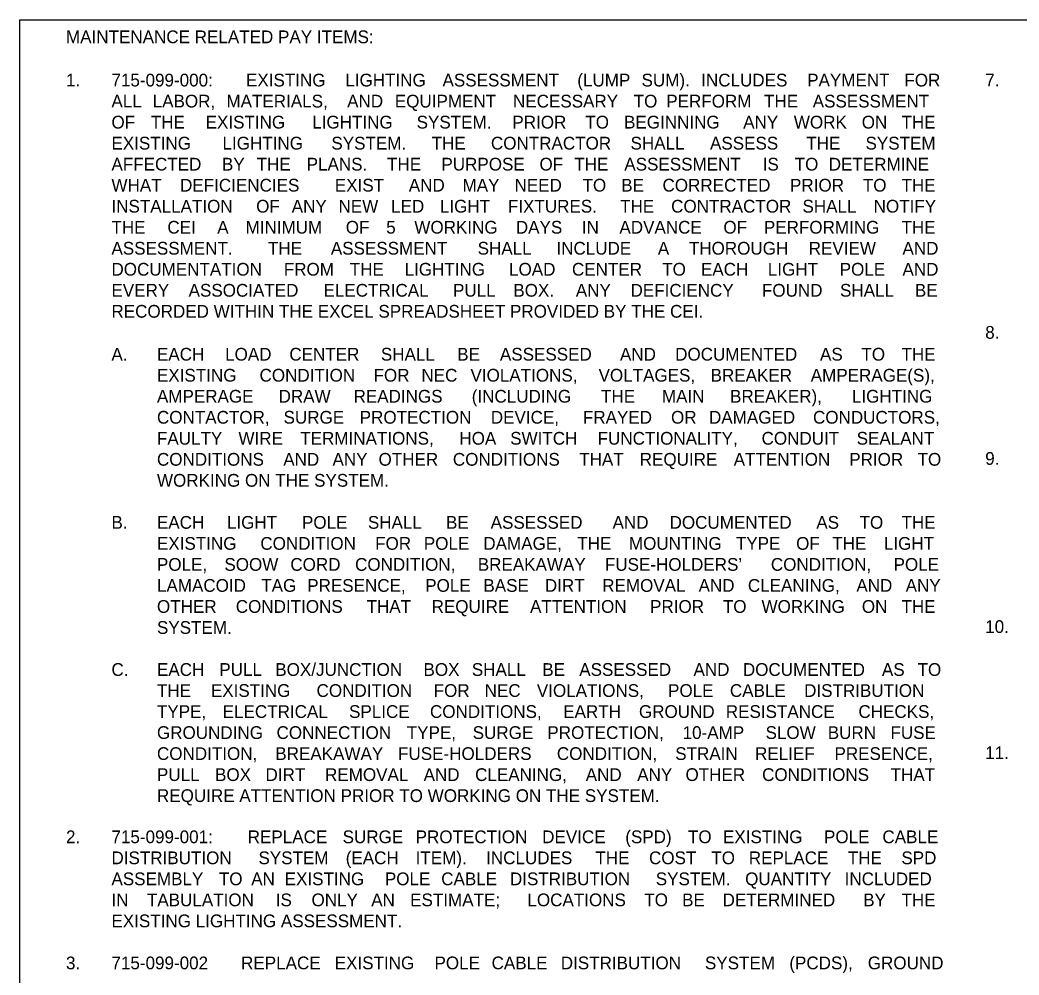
# Model space of a CAD drawing. Extents: x -55 to 2471539, y -90 to 3608906.
# Drawn here: x 0 to 543, y 440 to 960 of the extents above; entities that cross this region are included whole.
import ezdxf

# ---------------------------------------------------------------- set-up
doc = ezdxf.new("R2010")
doc.units = 0
doc.layers.add('NonPlottingEle_dp', color=7, linetype='Continuous')
doc.layers.add('TextNotes', color=7, linetype='Continuous')

msp = doc.modelspace()

# ---------------------------------------------------------------- linework, layer by layer
at = {"layer": 'NonPlottingEle_dp'}
msp.add_lwpolyline([(0, 0), (0, 960), (1540, 960), (1540, 0)], dxfattribs=at)

# ---------------------------------------------------------------- texts
at = {"layer": 'TextNotes'}
for s, p in [('MAINTENANCE RELATED PAY ITEMS:', (25.02, 947.36)), ('1.', (25.02, 923.83)), ('715-099-000: ', (49.75, 923.83)), ('EXISTING ', (122.93, 923.83)), ('LIGHTING ', (176.95, 923.83)), ('ASSESSMENT ', (229.81, 923.83)), ('(LUMP ', (303.12, 923.83)), ('SUM). ', (338.06, 923.83)), ('INCLUDES ', (370.51, 923.83)), ('PAYMENT ', (428.15, 923.83)), ('FOR ', (481.03, 923.83)), ('7.', (524.97, 923.83)), ('ALL ', (49.75, 912.39)), ('LABOR, ', (72.19, 912.39)), ('MATERIALS, ', (112.29, 912.39)), ('AND ', (177.94, 912.39)), ('EQUIPMENT ', (203.87, 912.39)), ('NECESSARY ', (268.15, 912.39)), ('TO ', (333.79, 912.39)), ('PERFORM ', (351.51, 912.39)), ('THE ', (404.7, 912.39)), ('ASSESSMENT ', (431.16, 912.39)), ('OF ', (49.75, 900.96)), ('THE ', (71.16, 900.96)), ('EXISTING ', (100.98, 900.96)), ('LIGHTING ', (158.95, 900.96)), ('SYSTEM. ', (215.73, 900.96)), ('PRIOR ', (267.82, 900.96)), ('TO ', (307.48, 900.96)), ('BEGINNING ', (328.55, 900.96)), ('ANY ', (393.34, 900.96)), ('WORK ', (420.89, 900.96)), ('ON ', (457.81, 900.96)), ('THE ', (479.44, 900.96)), ('EXISTING ', (49.75, 889.52)), ('LIGHTING ', (110.15, 889.52)), ('SYSTEM. ', (169.36, 889.52)), ('CONTRACTOR ', (256.14, 889.52)), ('SHALL ', (332.08, 889.52)), ('ASSESS ', (375.3, 889.52)), ('SYSTEM ', (459.88, 889.52)), ('THE ', (223.89, 889.52)), ('THE ', (427.64, 889.52)), ('AFFECTED ', (49.75, 878.09)), ('BY ', (109.86, 878.09)), ('THE ', (128.65, 878.09)), ('PLANS. ', (155.93, 878.09)), (' THE ', (197.09, 878.09)), ('PURPOSE ', (229.22, 878.09)), ('OF ', (282.55, 878.09)), ('THE ', (301.42, 878.09)), ('ASSESSMENT ', (328.69, 878.09)), ('IS ', (403.95, 878.09)), ('TO ', (421.35, 878.09)), ('DETERMINE ', (439.88, 878.09)), ('WHAT ', (49.75, 866.65)), ('DEFICIENCIES ', (87.07, 866.65)), ('EXIST ', (171.25, 866.65)), ('AND ', (211.47, 866.65)), ('MAY ', (240.69, 866.65)), ('NEED ', (268.96, 866.65)), ('TO ', (305.97, 866.65)), ('BE ', (326.99, 866.65)), ('CORRECTED ', (349.46, 866.65)), ('PRIOR ', (418.82, 866.65)), ('TO ', (458.42, 866.65)), ('THE ', (479.44, 866.65)), ('INSTALLATION ', (49.75, 855.22)), ('OF ', (128.46, 855.22)), ('ANY ', (147.79, 855.22)), ('NEW ', (173.26, 855.22)), ('LED ', (201.84, 855.22)), ('LIGHT ', (228.39, 855.22)), ('FIXTURES. ', (265.39, 855.22)), ('THE ', (326.41, 855.22)), ('CONTRACTOR ', (354.15, 855.22)), ('SHALL ', (425.59, 855.22)), ('NOTIFY ', (464.3, 855.22)), ('THE ', (49.75, 843.78)), ('CEI ', (80.17, 843.78)), ('A ', (107.28, 843.78)), ('MINIMUM ', (122.69, 843.78)), ('OF ', (177.18, 843.78)), ('5 ', (199.19, 843.78)), ('WORKING ', (214.48, 843.78)), ('DAYS ', (269.7, 843.78)), ('IN ', (305.6, 843.78)), ('ADVANCE ', (326.02, 843.78)), ('OF ', (382.58, 843.78)), ('PERFORMING ', (404.6, 843.78)), ('THE ', (479.44, 843.78)), ('ASSESSMENT. ', (49.75, 832.35)), (' THE ', (132.33, 832.35)), ('ASSESSMENT ', (169.07, 832.35)), ('SHALL ', (248.92, 832.35)), ('INCLUDE ', (291.76, 832.35)), ('A ', (346.93, 832.35)), ('THOROUGH ', (363.79, 832.35)), ('REVIEW ', (429, 832.35)), ('AND ', (479.97, 832.35)), ('DOCUMENTATION ', (49.75, 820.92)), ('FROM ', (143.48, 820.92)), ('THE ', (179.37, 820.92)), ('LIGHTING ', (209.2, 820.92)), ('LOAD ', (265.99, 820.92)), ('CENTER ', (300.22, 820.92)), ('TO ', (349.3, 820.92)), ('EACH ', (370.38, 820.92)), ('LIGHT ', (406.75, 820.92)), ('POLE ', (445.84, 820.92)), ('AND ', (479.97, 820.92)), ('EVERY ', (49.75, 809.48)), ('ASSOCIATED ', (91.71, 809.48)), ('ELECTRICAL ', (165.09, 809.48)), ('PULL ', (235.53, 809.48)), ('BOX. ', (268.34, 809.48)), (' ANY ', (299.73, 809.48)), ('DEFICIENCY ', (332.07, 809.48)), ('FOUND ', (403.54, 809.48)), ('SHALL ', (446.01, 809.48)), ('BE ', (486.73, 809.48)), ('RECORDED WITHIN THE EXCEL SPREADSHEET PROVIDED BY THE CEI. ', (49.75, 798.05)), ('8.', (524.97, 786.61)), ('A.', (49.75, 774.7)), ('EACH ', (74.5, 774.7)), ('LOAD ', (111.57, 774.7)), ('CENTER ', (146.5, 774.7)), ('SHALL ', (196.29, 774.7)), ('BE ', (237.79, 774.7)), ('ASSESSED ', (261.03, 774.7)), ('AND ', (326.33, 774.7)), ('DOCUMENTED ', (356.33, 774.7)), ('AS ', (435.12, 774.7)), ('TO ', (457.65, 774.7)), ('THE ', (479.44, 774.7)), ('EXISTING ', (74.5, 763.27)), ('CONDITION ', (130.29, 763.27)), ('FOR ', (192.29, 763.27)), ('NEC ', (218.32, 763.27)), ('VIOLATIONS, ', (245.02, 763.27)), ('VOLTAGES, ', (314.69, 763.27)), ('BREAKER ', (375.63, 763.27)), ('AMPERAGE(S), ', (430.08, 763.27)), ('AMPERAGE ', (74.5, 751.84)), ('DRAW ', (140.66, 751.84)), ('READINGS ', (181.43, 751.84)), ('(INCLUDING ', (245.7, 751.84)), ('THE ', (316.04, 751.84)), ('MAIN ', (349.13, 751.84)), ('BREAKER), ', (386.21, 751.84)), ('LIGHTING ', (452.48, 751.84)), ('CONTACTOR, ', (74.5, 740.4)), ('SURGE ', (143.35, 740.4)), ('PROTECTION ', (184.78, 740.4)), ('DEVICE, ', (256.09, 740.4)), ('FRAYED ', (306.17, 740.4)), ('OR ', (354.09, 740.4)), ('DAMAGED ', (374.76, 740.4)), ('CONDUCTORS, ', (431.31, 740.4)), ('FAULTY ', (74.5, 728.97)), ('WIRE ', (118.81, 728.97)), ('TERMINATIONS, ', (152.44, 728.97)), ('HOA ', (238.98, 728.97)), ('SWITCH ', (266.62, 728.97)), ('FUNCTIONALITY, ', (314.18, 728.97)), ('CONDUIT ', (403.34, 728.97)), ('SEALANT ', (455.05, 728.97)), ('CONDITIONS ', (74.5, 717.53)), ('AND ', (143.2, 717.53)), ('ANY ', (169.98, 717.53)), ('OTHER ', (195.02, 717.53)), ('CONDITIONS ', (235.45, 717.53)), ('THAT ', (304.15, 717.53)), ('REQUIRE ', (337.07, 717.53)), ('ATTENTION ', (388.19, 717.53)), ('PRIOR ', (451.02, 717.53)), ('TO ', (488.18, 717.53)), ('9.', (524.97, 718.01)), ('WORKING ON THE SYSTEM.', (74.5, 706.1)), ('B.', (49.75, 683.23)), ('EACH ', (74.5, 683.23)), ('LIGHT ', (112.58, 683.23)), ('POLE ', (153.38, 683.23)), ('SHALL ', (189.22, 683.23)), ('BE ', (231.74, 683.23)), ('ASSESSED ', (255.99, 683.23)), ('AND ', (322.29, 683.23)), ('DOCUMENTED ', (353.3, 683.23)), ('AS ', (433.1, 683.23)), ('TO ', (456.64, 683.23)), ('THE ', (479.44, 683.23)), ('EXISTING ', (74.5, 671.79)), ('CONDITION ', (130.73, 671.79)), ('FOR ', (193.17, 671.79)), ('POLE ', (219.65, 671.79)), ('DAMAGE, ', (252.02, 671.79)), ('THE ', (303.13, 671.79)), ('MOUNTING ', (331.2, 671.79)), ('TYPE ', (389.38, 671.79)), ('OF ', (422.14, 671.79)), ('THE ', (441.8, 671.79)), ('LIGHT ', (469.88, 671.79)), ('POLE, ', (74.5, 660.36)), ('SOOW ', (111.17, 660.36)), ('CORD ', (147.04, 660.36)), ('CONDITION, ', (182.24, 660.36)), ('BREAKAWAY ', (248.99, 660.36)), ('FUSE-HOLDERS’ ', (318.13, 660.36)), ('CONDITION, ', (408.4, 660.36)), ('POLE ', (475.14, 660.36)), ('LAMACOID ', (74.5, 648.92)), ('TAG ', (131.23, 648.92)), ('PRESENCE, ', (156.22, 648.92)), ('POLE ', (220.4, 648.92)), ('BASE ', (252.05, 648.92)), ('DIRT ', (285.47, 648.92)), ('REMOVAL ', (316.67, 648.92)), ('AND ', (369.09, 648.92)), ('CLEANING, ', (395.9, 648.92)), ('AND ', (454.89, 648.92)), ('ANY ', (481.71, 648.92)), ('OTHER ', (74.5, 637.49)), ('CONDITIONS ', (117.37, 637.49)), ('THAT ', (188.51, 637.49)), ('REQUIRE ', (223.87, 637.49)), ('ATTENTION ', (277.43, 637.49)), ('PRIOR ', (342.7, 637.49)), ('TO ', (382.3, 637.49)), ('WORKING ', (403.31, 637.49)), ('ON ', (457.87, 637.49)), ('THE ', (479.44, 637.49)), ('SYSTEM.', (74.5, 626.06)), ('10.', (524.97, 626.53)), ('C.', (49.75, 603.19)), ('EACH ', (74.5, 603.19)), ('PULL ', (108.42, 603.19)), ('BOX/JUNCTION ', (138.86, 603.19)), ('BOX ', (219.46, 603.19)), ('SHALL ', (245.74, 603.19)), ('BE ', (284.09, 603.19)), ('ASSESSED ', (304.18, 603.19)), ('AND ', (366.32, 603.19)), ('DOCUMENTED ', (393.17, 603.19)), ('AS ', (468.8, 603.19)), ('TO ', (488.18, 603.19)), ('THE ', (74.5, 591.75)), ('EXISTING ', (103.83, 591.75)), ('CONDITION ', (161.31, 591.75)), ('FOR ', (225, 591.75)), ('NEC ', (252.73, 591.75)), ('VIOLATIONS, ', (281.12, 591.75)), ('POLE ', (352.48, 591.75)), ('CABLE ', (386.11, 591.75)), ('DISTRIBUTION ', (426.48, 591.75)), ('TYPE, ', (74.5, 580.32)), ('ELECTRICAL ', (110.25, 580.32)), ('SPLICE ', (178.98, 580.32)), ('CONDITIONS, ', (222.99, 580.32)), ('EARTH ', (295.44, 580.32)), ('GROUND ', (336.64, 580.32)), ('RESISTANCE ', (383.89, 580.32)), ('CHECKS, ', (456.02, 580.32)), ('GROUNDING ', (74.5, 568.88)), ('CONNECTION ', (139.54, 568.88)), ('TYPE, ', (210.37, 568.88)), ('SURGE ', (246.21, 568.88)), ('PROTECTION, ', (286.84, 568.88)), ('10-AMP ', (360.39, 568.88)), ('SLOW ', (405.51, 568.88)), ('BURN ', (439.35, 568.88)), ('FUSE ', (473.44, 568.88)), ('CONDITION, ', (74.5, 557.45)), ('BREAKAWAY ', (138.87, 557.45)), ('FUSE-HOLDERS ', (205.64, 557.45)), ('CONDITION, ', (292, 557.45)), ('STRAIN ', (356.38, 557.45)), ('RELIEF ', (399.82, 557.45)), ('PRESENCE, ', (442.99, 557.45)), ('11.', (524.97, 557.92)), ('PULL ', (74.5, 546.01)), ('BOX ', (106.1, 546.01)), ('DIRT ', (133.54, 546.01)), ('REMOVAL ', (165.92, 546.01)), ('AND ', (219.53, 546.01)), ('CLEANING, ', (247.53, 546.01)), ('AND ', (307.7, 546.01)), ('ANY ', (335.71, 546.01)), ('OTHER ', (361.97, 546.01)), ('CONDITIONS ', (403.62, 546.01)), ('THAT ', (473.54, 546.01)), ('REQUIRE ATTENTION PRIOR TO WORKING ON THE SYSTEM.', (74.5, 534.58)), ('2.', (25.02, 512.18)), ('715-099-001: ', (49.75, 512.18)), ('REPLACE ', (123.87, 512.18)), ('SURGE ', (175.48, 512.18)), ('PROTECTION ', (215.21, 512.18)), ('DEVICE ', (284.01, 512.18)), ('(SPD) ', (329.21, 512.18)), ('TO ', (363.3, 512.18)), ('EXISTING ', (382.35, 512.18)), ('POLE ', (437.31, 512.18)), ('CABLE ', (469.06, 512.18)), ('DISTRIBUTION ', (49.75, 500.75)), ('SYSTEM ', (129.71, 500.75)), ('(EACH ', (177.17, 500.75)), ('ITEM). ', (215.19, 500.75)), ('INCLUDES ', (253.54, 500.75)), ('THE ', (312.98, 500.75)), ('COST ', (342.12, 500.75)), ('TO ', (376.01, 500.75)), ('REPLACE ', (396.4, 500.75)), ('THE ', (450.25, 500.75)), ('SPD ', (479.38, 500.75)), ('ASSEMBLY ', (49.75, 489.32)), ('TO ', (108.18, 489.32)), ('AN ', (125.77, 489.32)), ('EXISTING ', (143.97, 489.32)), ('POLE ', (198.47, 489.32)), ('CABLE ', (229.1, 489.32)), ('DISTRIBUTION ', (266.49, 489.32)), ('SYSTEM. ', (345.79, 489.32)), ('QUANTITY ', (394.41, 489.32)), ('INCLUDED ', (448.53, 489.32)), ('IN ', (49.75, 477.88)), ('TABULATION ', (69.05, 477.88)), ('IS ', (139.12, 477.88)), ('ONLY ', (158.56, 477.88)), ('AN ', (191.04, 477.88)), ('ESTIMATE; ', (212.21, 477.88)), ('LOCATIONS ', (275.99, 477.88)), ('TO ', (339.56, 477.88)), ('BE ', (360.12, 477.88)), ('DETERMINED ', (382.14, 477.88)), ('BY ', (458.61, 477.88)), ('THE ', (479.44, 477.88)), ('EXISTING LIGHTING ASSESSMENT.', (49.75, 466.45)), ('3.', (25.02, 443.58)), ('715-099-002 ', (49.75, 443.58)), ('REPLACE ', (120.26, 443.58)), ('EXISTING ', (171.18, 443.58)), ('POLE ', (225.45, 443.58)), ('CABLE ', (256.51, 443.58)), ('DISTRIBUTION ', (294.13, 443.58)), ('SYSTEM ', (372.54, 443.58)), ('(PCDS), ', (418.44, 443.58)), ('GROUND ', (461.11, 443.58))]:
    msp.add_text(s, height=6.93, dxfattribs=at).set_placement(p)

doc.saveas('drawing.dxf')
